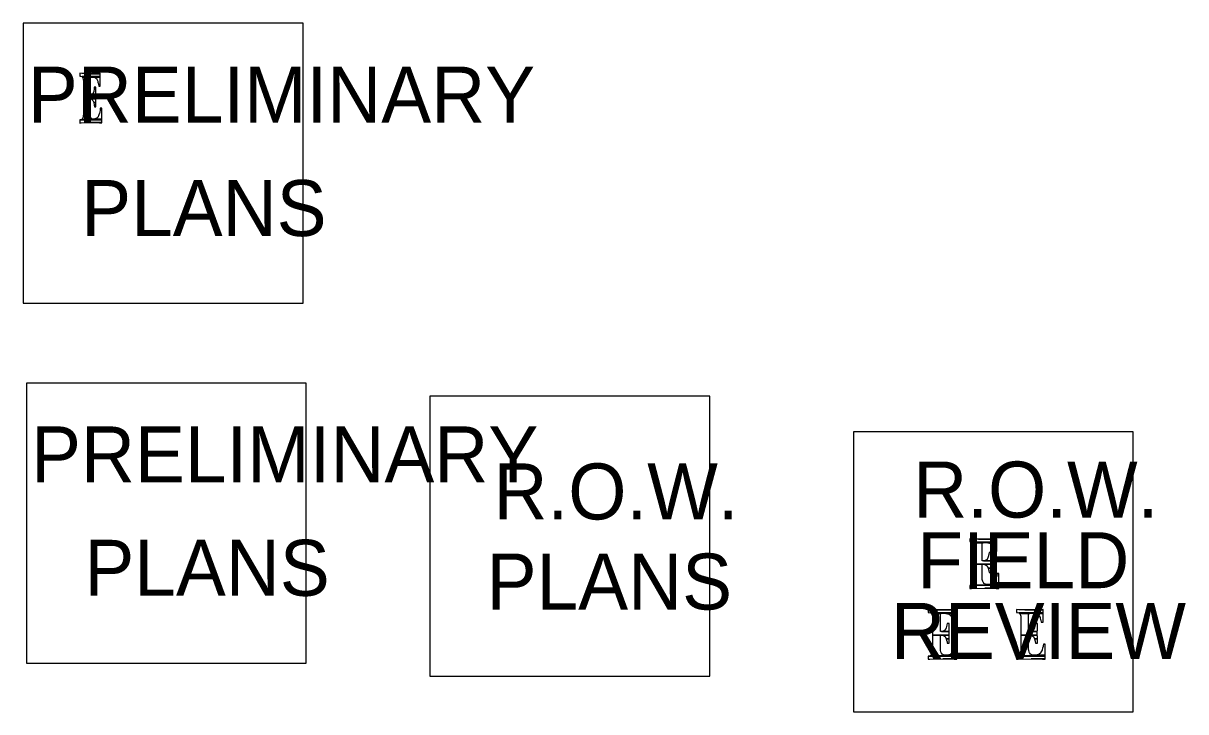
# Model space of a CAD drawing. Extents: x 1577619 to 1828281, y 483481 to 598136.
# Drawn here: x 1718349 to 1743281, y 517347 to 532101 of the extents above; entities that cross this region are included whole.
import ezdxf

# ---------------------------------------------------------------- set-up
doc = ezdxf.new("R2010")
doc.units = 0
doc.layers.add('DESIGN - SHEET - Corner Text', color=7, linetype='Continuous')

msp = doc.modelspace()

# ---------------------------------------------------------------- linework, layer by layer
at = {"layer": 'DESIGN - SHEET - Corner Text'}
for points in [[(1718349, 532101), (1718349, 526101), (1724349, 526101), (1724349, 532101)], [(1719585, 530967), (1719609, 530958), (1720000, 530958), (1720000, 530967), (1720000, 530969), (1720000, 531021), (1719705, 531021), (1719678, 531022), (1719609, 531026), (1719606, 531026), (1719605, 531026), (1719566, 531030), (1719566, 531026), (1719566, 531026), (1719566, 531022), (1719566, 531021), (1719566, 530969)], [(1719615, 530949), (1719617, 530946), (1719777, 530946), (1719823, 530949), (1720000, 530949), (1720000, 530958), (1719609, 530958)], [(1719764, 530483), (1719904, 530483), (1719903, 530526), (1719904, 530555), (1719764, 530555), (1719764, 530563), (1719764, 530588), (1719764, 530640), (1719764, 530696), (1719764, 530698), (1719764, 530755), (1719764, 530800), (1719764, 530817), (1719764, 530841), (1719764, 530857), (1719764, 530891), (1719764, 530901), (1719764, 530909), (1719764, 530909), (1719764, 530926), (1719765, 530930), (1719765, 530930), (1719766, 530932), (1719766, 530932), (1719768, 530939), (1719775, 530945), (1719777, 530946), (1719823, 530949), (1719615, 530949), (1719617, 530946), (1719618, 530945), (1719621, 530939), (1719626, 530932), (1719627, 530930), (1719628, 530926), (1719632, 530909), (1719634, 530901), (1719637, 530891), (1719639, 530857), (1719640, 530841), (1719640, 530817), (1719640, 530800), (1719640, 530755), (1719640, 530698), (1719640, 530696), (1719640, 530640), (1719640, 530588), (1719640, 530563), (1719640, 530555), (1719640, 530526), (1719640, 530483)], [(1719813, 531022), (1719705, 531021), (1720000, 531021), (1720000, 531022), (1720000, 531026), (1720000, 531026), (1720000, 531031), (1719920, 531026), (1719910, 531026)], [(1719852, 530946), (1719866, 530945), (1720000, 530945), (1720000, 530946), (1720000, 530949), (1719823, 530949)], [(1719961, 530800), (1719968, 530755), (1720000, 530755), (1720000, 530800), (1720000, 530817), (1720000, 530841), (1720000, 530857), (1720000, 530891), (1720000, 530901), (1720000, 530909), (1720000, 530926), (1720000, 530930), (1720000, 530932), (1720000, 530939), (1720000, 530945), (1719866, 530945), (1719881, 530939), (1719900, 530932), (1719902, 530930), (1719906, 530926), (1719926, 530909), (1719930, 530901), (1719934, 530891), (1719949, 530857), (1719952, 530841), (1719958, 530817)], [(1719813, 530563), (1719784, 530555), (1719904, 530555), (1719904, 530563), (1719904, 530588), (1719905, 530640), (1719906, 530696), (1719906, 530698), (1719908, 530733), (1719873, 530733), (1719869, 530698), (1719869, 530696), (1719860, 530640), (1719842, 530588)], [(1719640, 530483), (1719640, 530482), (1719640, 530475), (1719640, 530449), (1719640, 530402), (1719640, 530348), (1719640, 530342), (1719640, 530307), (1719640, 530252), (1719640, 530235), (1719640, 530202), (1719639, 530170), (1719639, 530167), (1719639, 530160), (1719636, 530116), (1719635, 530102), (1719632, 530093), (1719626, 530074), (1719621, 530057), (1719621, 530055), (1719618, 530053), (1719612, 530048), (1719599, 530037), (1720032, 530037), (1720032, 530048), (1719864, 530048), (1719820, 530053), (1719817, 530055), (1719817, 530055), (1719815, 530057), (1719791, 530074), (1719783, 530093), (1719779, 530102), (1719772, 530116), (1719765, 530160), (1719765, 530167), (1719765, 530170), (1719764, 530202), (1719764, 530235), (1719764, 530252), (1719764, 530307), (1719764, 530342), (1719764, 530348), (1719764, 530402), (1719764, 530449), (1719764, 530475), (1719764, 530482), (1719764, 530483)], [(1719764, 530483), (1719783, 530482), (1719904, 530482), (1719904, 530483)], [(1719844, 530449), (1719861, 530402), (1719905, 530402), (1719904, 530449), (1719904, 530449), (1719904, 530475), (1719904, 530482), (1719783, 530482), (1719815, 530475)], [(1719871, 530342), (1719875, 530307), (1719907, 530307), (1719906, 530342), (1719906, 530348), (1719905, 530402), (1719860, 530402), (1719870, 530348)], [(1719887, 530053), (1719864, 530048), (1720032, 530048), (1720032, 530053), (1720032, 530055), (1720032, 530057), (1720032, 530074), (1720032, 530093), (1720032, 530102), (1720032, 530116), (1720032, 530160), (1720032, 530167), (1720032, 530170), (1720032, 530202), (1720032, 530235), (1720032, 530252), (1720032, 530285), (1720002, 530285), (1719999, 530252), (1719996, 530235), (1719990, 530202), (1719984, 530170), (1719983, 530167), (1719980, 530160), (1719963, 530116), (1719957, 530102), (1719953, 530093), (1719931, 530074), (1719909, 530057), (1719901, 530055)], [(1719566, 529965), (1719566, 529963), (1719576, 529965), (1719593, 529967), (1719807, 529974), (1720032, 529974), (1720032, 530030), (1720032, 530032), (1719580, 530032), (1719566, 530030), (1719566, 529974), (1719566, 529967)], [(1719599, 530037), (1719580, 530032), (1720032, 530032), (1720032, 530037)], [(1719987, 529967), (1720032, 529965), (1720032, 529967), (1720032, 529974), (1719807, 529974)], [(1718416, 524391), (1718416, 518391), (1724416, 518391), (1724416, 524391)], [(1727071, 524111), (1727071, 518111), (1733071, 518111), (1733071, 524111)], [(1736153, 523347), (1736153, 517347), (1742153, 517347), (1742153, 523347)], [(1738679, 520991), (1738710, 520982), (1739231, 520982), (1739231, 520991), (1739231, 520993), (1739231, 521045), (1738838, 521045), (1738802, 521046), (1738711, 521050), (1738705, 521050), (1738705, 521050), (1738653, 521054), (1738653, 521050), (1738653, 521050), (1738653, 521046), (1738653, 521045), (1738653, 520993)], [(1738718, 520973), (1738720, 520970), (1738935, 520970), (1738995, 520973), (1739231, 520973), (1739231, 520982), (1738710, 520982)], [(1738916, 520507), (1739103, 520507), (1739103, 520550), (1739103, 520579), (1738916, 520579), (1738916, 520587), (1738916, 520612), (1738916, 520664), (1738916, 520720), (1738916, 520722), (1738916, 520779), (1738916, 520824), (1738916, 520840), (1738916, 520865), (1738916, 520880), (1738916, 520915), (1738916, 520925), (1738917, 520933), (1738917, 520933), (1738917, 520950), (1738919, 520954), (1738918, 520954), (1738919, 520955), (1738919, 520955), (1738922, 520963), (1738932, 520968), (1738935, 520970), (1738995, 520973), (1738718, 520973), (1738720, 520970), (1738722, 520968), (1738726, 520963), (1738733, 520955), (1738735, 520954), (1738736, 520950), (1738741, 520933), (1738744, 520925), (1738747, 520915), (1738750, 520880), (1738751, 520865), (1738752, 520840), (1738752, 520824), (1738752, 520779), (1738752, 520722), (1738752, 520720), (1738752, 520664), (1738752, 520612), (1738752, 520587), (1738752, 520579), (1738752, 520550), (1738752, 520507)], [(1738982, 521046), (1738838, 521045), (1739231, 521045), (1739231, 521046), (1739231, 521050), (1739231, 521050), (1739231, 521054), (1739124, 521050), (1739111, 521050)], [(1739034, 520970), (1739053, 520968), (1739231, 520968), (1739231, 520970), (1739231, 520973), (1738995, 520973)], [(1739180, 520824), (1739189, 520779), (1739231, 520779), (1739231, 520824), (1739231, 520840), (1739231, 520865), (1739231, 520880), (1739231, 520915), (1739231, 520925), (1739231, 520933), (1739231, 520950), (1739231, 520954), (1739231, 520955), (1739231, 520963), (1739231, 520968), (1739053, 520968), (1739072, 520963), (1739098, 520955), (1739101, 520954), (1739106, 520950), (1739133, 520933), (1739137, 520925), (1739143, 520915), (1739163, 520880), (1739167, 520865), (1739175, 520840)], [(1738982, 520587), (1738943, 520579), (1739103, 520579), (1739103, 520587), (1739104, 520612), (1739105, 520664), (1739106, 520720), (1739106, 520722), (1739108, 520756), (1739062, 520756), (1739057, 520722), (1739057, 520720), (1739044, 520664), (1739021, 520612)], [(1738752, 520507), (1738752, 520506), (1738752, 520498), (1738752, 520472), (1738752, 520426), (1738752, 520372), (1738752, 520365), (1738752, 520331), (1738752, 520276), (1738752, 520258), (1738751, 520226), (1738750, 520194), (1738750, 520190), (1738749, 520183), (1738745, 520140), (1738744, 520125), (1738740, 520116), (1738733, 520098), (1738726, 520080), (1738725, 520079), (1738721, 520076), (1738715, 520072), (1738697, 520061), (1739274, 520061), (1739274, 520072), (1739050, 520072), (1738991, 520076), (1738987, 520079), (1738987, 520079), (1738984, 520080), (1738953, 520098), (1738942, 520116), (1738936, 520125), (1738928, 520140), (1738918, 520183), (1738918, 520190), (1738918, 520194), (1738916, 520226), (1738916, 520258), (1738916, 520276), (1738916, 520331), (1738916, 520365), (1738916, 520372), (1738916, 520426), (1738916, 520472), (1738916, 520498), (1738916, 520506), (1738916, 520507)], [(1738916, 520507), (1738942, 520506), (1739103, 520506), (1739103, 520507)], [(1739023, 520472), (1739045, 520426), (1739105, 520426), (1739104, 520472), (1739104, 520472), (1739103, 520498), (1739103, 520506), (1738942, 520506), (1738984, 520498)], [(1739059, 520365), (1739065, 520331), (1739107, 520331), (1739106, 520365), (1739106, 520372), (1739105, 520426), (1739045, 520426), (1739058, 520372)], [(1739081, 520076), (1739050, 520072), (1739274, 520072), (1739274, 520076), (1739274, 520079), (1739274, 520080), (1739274, 520098), (1739274, 520116), (1739274, 520125), (1739274, 520140), (1739274, 520183), (1739274, 520190), (1739274, 520194), (1739274, 520226), (1739274, 520258), (1739274, 520276), (1739274, 520308), (1739234, 520308), (1739230, 520276), (1739226, 520258), (1739218, 520226), (1739210, 520194), (1739209, 520190), (1739205, 520183), (1739182, 520140), (1739174, 520125), (1739169, 520116), (1739139, 520098), (1739109, 520080), (1739099, 520079)], [(1738653, 519989), (1738653, 519987), (1738666, 519989), (1738689, 519991), (1738973, 519998), (1739274, 519998), (1739274, 520054), (1739274, 520056), (1738671, 520056), (1738653, 520054), (1738653, 519998), (1738653, 519991)], [(1738697, 520061), (1738671, 520056), (1739274, 520056), (1739274, 520061)], [(1739214, 519991), (1739274, 519989), (1739274, 519991), (1739274, 519998), (1738973, 519998)], [(1737780, 519475), (1737811, 519466), (1738332, 519466), (1738332, 519475), (1738332, 519477), (1738332, 519529), (1737939, 519529), (1737903, 519530), (1737812, 519534), (1737806, 519534), (1737806, 519534), (1737754, 519538), (1737754, 519534), (1737754, 519534), (1737754, 519530), (1737754, 519529), (1737754, 519477)], [(1737819, 519457), (1737821, 519454), (1738036, 519454), (1738096, 519457), (1738332, 519457), (1738332, 519466), (1737811, 519466)], [(1738018, 518991), (1738204, 518991), (1738204, 519034), (1738204, 519063), (1738018, 519063), (1738018, 519071), (1738018, 519096), (1738018, 519148), (1738018, 519204), (1738018, 519206), (1738018, 519263), (1738018, 519308), (1738018, 519324), (1738018, 519349), (1738018, 519364), (1738018, 519399), (1738018, 519409), (1738018, 519417), (1738018, 519417), (1738018, 519434), (1738020, 519438), (1738020, 519438), (1738020, 519439), (1738020, 519439), (1738023, 519447), (1738033, 519452), (1738036, 519454), (1738096, 519457), (1737819, 519457), (1737821, 519454), (1737823, 519452), (1737828, 519447), (1737834, 519439), (1737836, 519438), (1737837, 519434), (1737842, 519417), (1737845, 519409), (1737848, 519399), (1737851, 519364), (1737852, 519349), (1737853, 519324), (1737853, 519308), (1737853, 519263), (1737853, 519206), (1737853, 519204), (1737853, 519148), (1737853, 519096), (1737853, 519071), (1737853, 519063), (1737853, 519034), (1737853, 518991)], [(1738083, 519530), (1737939, 519529), (1738332, 519529), (1738332, 519530), (1738332, 519534), (1738332, 519534), (1738332, 519538), (1738225, 519534), (1738212, 519534)], [(1738135, 519454), (1738154, 519452), (1738332, 519452), (1738332, 519454), (1738332, 519457), (1738096, 519457)], [(1738281, 519308), (1738290, 519263), (1738332, 519263), (1738332, 519308), (1738332, 519324), (1738332, 519349), (1738332, 519364), (1738332, 519399), (1738332, 519409), (1738332, 519417), (1738332, 519434), (1738332, 519438), (1738332, 519439), (1738332, 519447), (1738332, 519452), (1738154, 519452), (1738174, 519447), (1738199, 519439), (1738202, 519438), (1738208, 519434), (1738234, 519417), (1738238, 519409), (1738244, 519399), (1738264, 519364), (1738268, 519349), (1738276, 519324)], [(1739673, 519475), (1739704, 519466), (1740226, 519466), (1740226, 519475), (1740226, 519477), (1740226, 519529), (1739833, 519529), (1739796, 519530), (1739705, 519534), (1739700, 519534), (1739700, 519534), (1739648, 519538), (1739648, 519534), (1739648, 519534), (1739648, 519530), (1739648, 519529), (1739648, 519477)], [(1739712, 519457), (1739715, 519454), (1739929, 519454), (1739990, 519457), (1740226, 519457), (1740226, 519466), (1739704, 519466)], [(1739911, 518991), (1740098, 518991), (1740097, 519034), (1740098, 519063), (1739911, 519063), (1739911, 519071), (1739911, 519096), (1739911, 519148), (1739911, 519204), (1739911, 519206), (1739911, 519263), (1739911, 519308), (1739911, 519324), (1739911, 519349), (1739911, 519364), (1739911, 519399), (1739911, 519409), (1739911, 519417), (1739911, 519417), (1739912, 519434), (1739913, 519438), (1739913, 519438), (1739914, 519439), (1739914, 519439), (1739917, 519447), (1739927, 519452), (1739929, 519454), (1739990, 519457), (1739712, 519457), (1739715, 519454), (1739716, 519452), (1739721, 519447), (1739728, 519439), (1739729, 519438), (1739730, 519434), (1739736, 519417), (1739739, 519409), (1739742, 519399), (1739744, 519364), (1739746, 519349), (1739746, 519324), (1739746, 519308), (1739746, 519263), (1739746, 519206), (1739746, 519204), (1739746, 519148), (1739746, 519096), (1739746, 519071), (1739746, 519063), (1739746, 519034), (1739746, 518991)], [(1739977, 519530), (1739833, 519529), (1740226, 519529), (1740226, 519530), (1740226, 519534), (1740226, 519534), (1740226, 519538), (1740119, 519534), (1740106, 519534)], [(1740028, 519454), (1740048, 519452), (1740226, 519452), (1740226, 519454), (1740226, 519457), (1739990, 519457)], [(1740174, 519308), (1740183, 519263), (1740226, 519263), (1740226, 519308), (1740226, 519324), (1740226, 519349), (1740226, 519364), (1740226, 519399), (1740226, 519409), (1740226, 519417), (1740226, 519434), (1740226, 519438), (1740226, 519439), (1740226, 519447), (1740226, 519452), (1740048, 519452), (1740067, 519447), (1740093, 519439), (1740096, 519438), (1740101, 519434), (1740127, 519417), (1740132, 519409), (1740137, 519399), (1740157, 519364), (1740162, 519349), (1740169, 519324)], [(1738083, 519071), (1738044, 519063), (1738204, 519063), (1738204, 519071), (1738205, 519096), (1738206, 519148), (1738207, 519204), (1738207, 519206), (1738209, 519240), (1738163, 519240), (1738158, 519206), (1738158, 519204), (1738146, 519148), (1738122, 519096)], [(1739977, 519071), (1739938, 519063), (1740098, 519063), (1740098, 519071), (1740099, 519096), (1740100, 519148), (1740101, 519204), (1740101, 519206), (1740103, 519240), (1740057, 519240), (1740052, 519206), (1740051, 519204), (1740039, 519148), (1740016, 519096)], [(1737853, 518991), (1737853, 518990), (1737853, 518982), (1737853, 518956), (1737853, 518910), (1737853, 518856), (1737853, 518849), (1737853, 518815), (1737853, 518760), (1737853, 518742), (1737852, 518710), (1737851, 518678), (1737851, 518674), (1737850, 518667), (1737846, 518624), (1737845, 518609), (1737841, 518600), (1737834, 518582), (1737827, 518564), (1737826, 518563), (1737822, 518560), (1737816, 518556), (1737798, 518545), (1738375, 518545), (1738375, 518556), (1738151, 518556), (1738092, 518560), (1738088, 518563), (1738088, 518563), (1738085, 518564), (1738054, 518582), (1738043, 518600), (1738038, 518609), (1738029, 518624), (1738019, 518667), (1738019, 518674), (1738019, 518678), (1738018, 518710), (1738018, 518742), (1738018, 518760), (1738018, 518815), (1738018, 518849), (1738018, 518856), (1738018, 518910), (1738018, 518956), (1738018, 518982), (1738018, 518990), (1738018, 518991)], [(1738017, 518991), (1738043, 518990), (1738204, 518990), (1738204, 518991)], [(1738124, 518956), (1738146, 518910), (1738206, 518910), (1738205, 518956), (1738205, 518956), (1738205, 518982), (1738204, 518990), (1738043, 518990), (1738085, 518982)], [(1738161, 518849), (1738166, 518815), (1738208, 518815), (1738207, 518849), (1738207, 518856), (1738206, 518910), (1738146, 518910), (1738160, 518856)], [(1739746, 518991), (1739746, 518990), (1739746, 518982), (1739746, 518956), (1739746, 518910), (1739746, 518856), (1739746, 518849), (1739746, 518815), (1739746, 518760), (1739746, 518742), (1739746, 518710), (1739745, 518678), (1739745, 518674), (1739744, 518667), (1739740, 518624), (1739739, 518609), (1739735, 518600), (1739728, 518582), (1739721, 518564), (1739720, 518563), (1739716, 518560), (1739709, 518556), (1739692, 518545), (1740268, 518545), (1740268, 518556), (1740044, 518556), (1739986, 518560), (1739982, 518563), (1739981, 518563), (1739979, 518564), (1739948, 518582), (1739937, 518600), (1739931, 518609), (1739923, 518624), (1739913, 518667), (1739912, 518674), (1739912, 518678), (1739911, 518710), (1739911, 518742), (1739911, 518760), (1739911, 518815), (1739911, 518849), (1739911, 518856), (1739911, 518910), (1739911, 518956), (1739911, 518982), (1739911, 518990), (1739911, 518991)], [(1739911, 518991), (1739937, 518990), (1740098, 518990), (1740098, 518991)], [(1740018, 518956), (1740040, 518910), (1740099, 518910), (1740099, 518956), (1740099, 518956), (1740098, 518982), (1740098, 518990), (1739937, 518990), (1739979, 518982)], [(1740054, 518849), (1740059, 518815), (1740102, 518815), (1740100, 518849), (1740100, 518856), (1740099, 518910), (1740040, 518910), (1740053, 518856)], [(1738182, 518560), (1738151, 518556), (1738375, 518556), (1738375, 518560), (1738375, 518563), (1738375, 518564), (1738375, 518582), (1738375, 518600), (1738375, 518609), (1738375, 518624), (1738375, 518667), (1738375, 518674), (1738375, 518678), (1738375, 518710), (1738375, 518742), (1738375, 518760), (1738375, 518792), (1738335, 518792), (1738331, 518760), (1738327, 518742), (1738319, 518710), (1738311, 518678), (1738310, 518674), (1738306, 518667), (1738283, 518624), (1738275, 518609), (1738270, 518600), (1738240, 518582), (1738210, 518564), (1738200, 518563)], [(1740075, 518560), (1740044, 518556), (1740268, 518556), (1740268, 518560), (1740268, 518563), (1740268, 518564), (1740268, 518582), (1740268, 518600), (1740268, 518609), (1740268, 518624), (1740268, 518667), (1740268, 518674), (1740268, 518678), (1740268, 518710), (1740268, 518742), (1740268, 518760), (1740268, 518792), (1740229, 518792), (1740225, 518760), (1740220, 518742), (1740212, 518710), (1740204, 518678), (1740204, 518674), (1740200, 518667), (1740176, 518624), (1740169, 518609), (1740164, 518600), (1740134, 518582), (1740104, 518564), (1740094, 518563)], [(1737754, 518473), (1737754, 518471), (1737767, 518473), (1737790, 518475), (1738074, 518482), (1738375, 518482), (1738375, 518538), (1738375, 518540), (1737772, 518540), (1737754, 518538), (1737754, 518482), (1737754, 518475)], [(1737798, 518545), (1737772, 518540), (1738375, 518540), (1738375, 518545)], [(1738315, 518475), (1738375, 518473), (1738375, 518475), (1738375, 518482), (1738074, 518482)], [(1739648, 518473), (1739648, 518471), (1739661, 518473), (1739684, 518475), (1739968, 518482), (1740268, 518482), (1740268, 518538), (1740268, 518540), (1739666, 518540), (1739648, 518538), (1739648, 518482), (1739648, 518475)], [(1739692, 518545), (1739666, 518540), (1740268, 518540), (1740268, 518545)], [(1740208, 518475), (1740268, 518473), (1740268, 518475), (1740268, 518482), (1739968, 518482)]]:
    msp.add_lwpolyline(points, close=True, dxfattribs=at)

# ---------------------------------------------------------------- texts
for s, p in [('PRELIMINARY', (1718448, 529971)), ('PLANS', (1719592, 527541)), ('PRELIMINARY', (1718516, 522261)), ('R.O.W.', (1728433, 521468)), ('R.O.W.', (1737436, 521508)), ('FIELD', (1737523, 519995)), ('PLANS', (1719660, 519831)), ('PLANS', (1728288, 519537)), ('REVIEW', (1736956, 518479))]:
    msp.add_text(s, height=1200, dxfattribs=at).set_placement(p)

doc.saveas('drawing.dxf')
